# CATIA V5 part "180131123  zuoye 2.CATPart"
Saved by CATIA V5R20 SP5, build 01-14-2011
Part number: zuoye
Bounding box of the stored display mesh (mm): x -3.244 to 20, y -47.623 to 47.623, z -47.623 to 47.623
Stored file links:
  E:\180131123\180131123  zuoye 2.CATPart
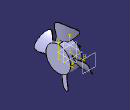
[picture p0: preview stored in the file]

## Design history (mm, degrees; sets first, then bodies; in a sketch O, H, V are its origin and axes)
Body1 (main body)
  Sketch1 on yz-plane, origin (0, 0, 0), H (0, 1, 0), V (0, 0, 1)
    circle A1 centre (0, 0) radius 21.5
    radius A1 = 21.5
  Pad1: profile Sketch1, direction (1, 0, 0), length 20
  Shell1: ExtOffset 0, Face start face of Pad1, IntOffset 1
  Sketch2 on yz-plane, origin (0, 0, 0), H (0, 1, 0), V (0, 0, 1)
    reference projected circle E1 centre (0, 0) radius 20.5 from edge [face of Shell1 | start face of Pad1]
    reference projected circle E2 centre (0, 0) radius 21.5 from edge [start face of Pad1 | face of Pad1 from Sketch1.A1]
    distance O E1 = 20
    distance O E2 = 21.5
  Plane1: type Offset, RefPlane zx-plane, Offset 33
  Sketch3 on Plane1, origin (0, 33, 0), H (-1, 0, 0), V (0, 0, 1)
    spline S1 through (-15.6048, 14.7076) (-9.2603, -2.3991) (3.0682, -15.4088)
    offsetcurve C1
    construction line L1 (-15.6048, 14.7076) -> (-15.309, 14.7575)
    point P3 (-15.6048, 14.7076)
    construction line L2 through (-15.6048, 14.7076) direction (-0.1663, 0.9861)
    construction line L3 (3.0682, -15.4088) -> (3.2443, -15.1659)
    point P4 (3.0682, -15.4088)
    construction line L4 through (3.0682, -15.4088) direction (0.8096, -0.587)
    line L5 (3.0682, -15.4088) -> (3.2443, -15.1659)
    point P5 (3.0682, -15.4088)
    line L6 (-15.6048, 14.7076) -> (-15.309, 14.7575)
    point P6 (-15.6048, 14.7076)
    point P7 (-15.6048, 14.7076)
    point P8 (3.0682, -15.4088)
    coincidence: P7 P3, P8 P4, P8 P5, P7 P6
    tangency: L2 S1, L4 S1
    perpendicularity: L1 L2, L3 L4
  Pad2: profile Sketch3, direction (0, 1, 0), length 20, opposite side length 19
  Sketch4 on yz-plane, origin (0, 0, 0), H (0, 1, 0), V (0, 0, 1)
  Sketch5 on end face of Pad1, origin (20, 0, 0), H (0, 1, 0), V (0, 0, 1)
    arc A1 centre (0, 0) radius 21.5 from (14.6194, -15.7646) to (20.9764, -4.7162) ccw
    line L1 (15.3804, 15.0231) -> (53.2864, 15.0231)
    line L2 (53.2864, 15.0231) -> (53.2864, -15.7646)
    line L3 (53.2864, -15.7646) -> (14.6194, -15.7646)
    spline S1 through (18.3434, 11.2147) (25.9621, 9.0784) (36.6417, 11.2147) (44.5311, 11.2147) (42.5106, -8.7626) (36.0644, -14.7095) (25.481, -8.7626) (20.9764, -4.7162)
    arc A2 centre (0, 0) radius 21.5 from (18.3434, 11.2147) to (15.3804, 15.0231) ccw
    point P5 (20.9764, -4.7162)
    point P6 (18.3434, 11.2147)
    point P7 (18.3434, 11.2147)
    point P8 (20.9764, -4.7162)
    radius A1 = 21.5
    horizontal: L1 H, L3 H
    vertical: L2 V
    coincidence: P7 A1, P8 A1, P8 P5, P7 P6, A1 A2
  Sketch6 on end face of Pad1, origin (20, 0, 0), H (0, 1, 0), V (0, 0, 1)
  Sketch7 on end face of Pad1, origin (20, 0, 0), H (0, 1, 0), V (0, 0, 1)
  Pocket1: profile Sketch5, direction (-1, 0, 0), length 25
  CircPattern1: of the body so far, instances 4, angular step 90, axis from face of Shell1
  Sketch8 on end face of Pad1, origin (20, 0, 0), H (0, 1, 0), V (0, 0, 1)
    arc A1 centre (0, 0) radius 21.5 from (20.7811, -5.5133) to (18.2194, 11.4151) ccw
    spline S1 through (18.2194, 11.4151) (25.3512, 10.7358) (35.4697, 13.2842) (43.458, 10.7358) (42.6059, -8.6962) (35.4697, -14.5365) (27.4814, -11.2447) (20.7811, -5.5133)
    point P1 (18.2194, 11.4151)
    point P2 (20.7811, -5.5133)
    point P3 (18.2194, 11.4151)
    point P4 (20.7811, -5.5133)
    radius A1 = 21.5
    coincidence: P3 A1, P4 A1, P3 P1, P4 P2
